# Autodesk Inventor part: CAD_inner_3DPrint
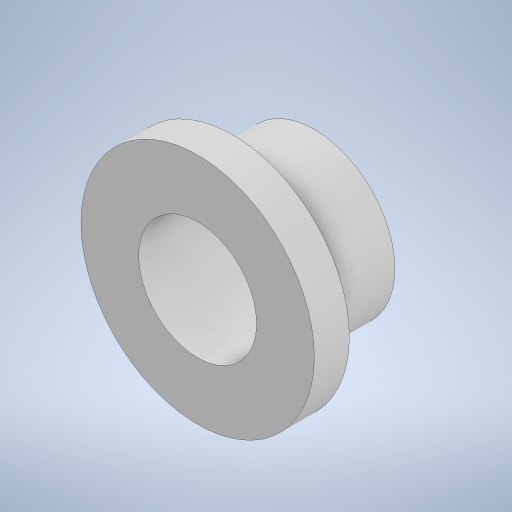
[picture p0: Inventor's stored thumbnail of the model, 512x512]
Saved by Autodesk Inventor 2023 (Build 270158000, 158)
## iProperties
Created: 2023-04
Part Number: CAD_inner_3DPrint
Material: Generic
Document SubType Name: Modeling
Designer: steff
Density: 1 g/cm^3
Appearance: Default
Author: steff
Part Number: CAD_inner_3
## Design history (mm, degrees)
sketch "Sketch1"
  geometry: C1 r 5.05 at (0, 0); C2 r 6.9 at (0, 0); 1 further point
  constraints: 2 centre point, 2 coincident
  dimensions: "d0" = 10.1 diameter of C1; "d1" = 13.8 diameter of C2
extrude "Extrusion1" new body sketch "Sketch1" distance "d2" = 10; taper "d3" = 0 deg
sketch "Sketch2"
  geometry: C1 r 10 at (0, 0); C2 r 6.9 at (0, 0) reference; 1 further point
  constraints: 1 centre point, 1 coincident
  dimensions: "d4" = 20 diameter of C1
extrude "Extrusion2" join sketch "Sketch2" distance "d6" = 3; taper "d7" = 0 deg
sketch "Sketch3"
  geometry: 1 further point
sketch "Sketch4"
  geometry: 1 further point
body "Solid1"
